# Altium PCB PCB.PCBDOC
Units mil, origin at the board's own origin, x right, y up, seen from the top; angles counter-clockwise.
Board outline 6000 x 4000 mil, 2 copper layers (Top Layer, Bottom Layer); 12 components, 5 nets, 24 pads, 0 vias.
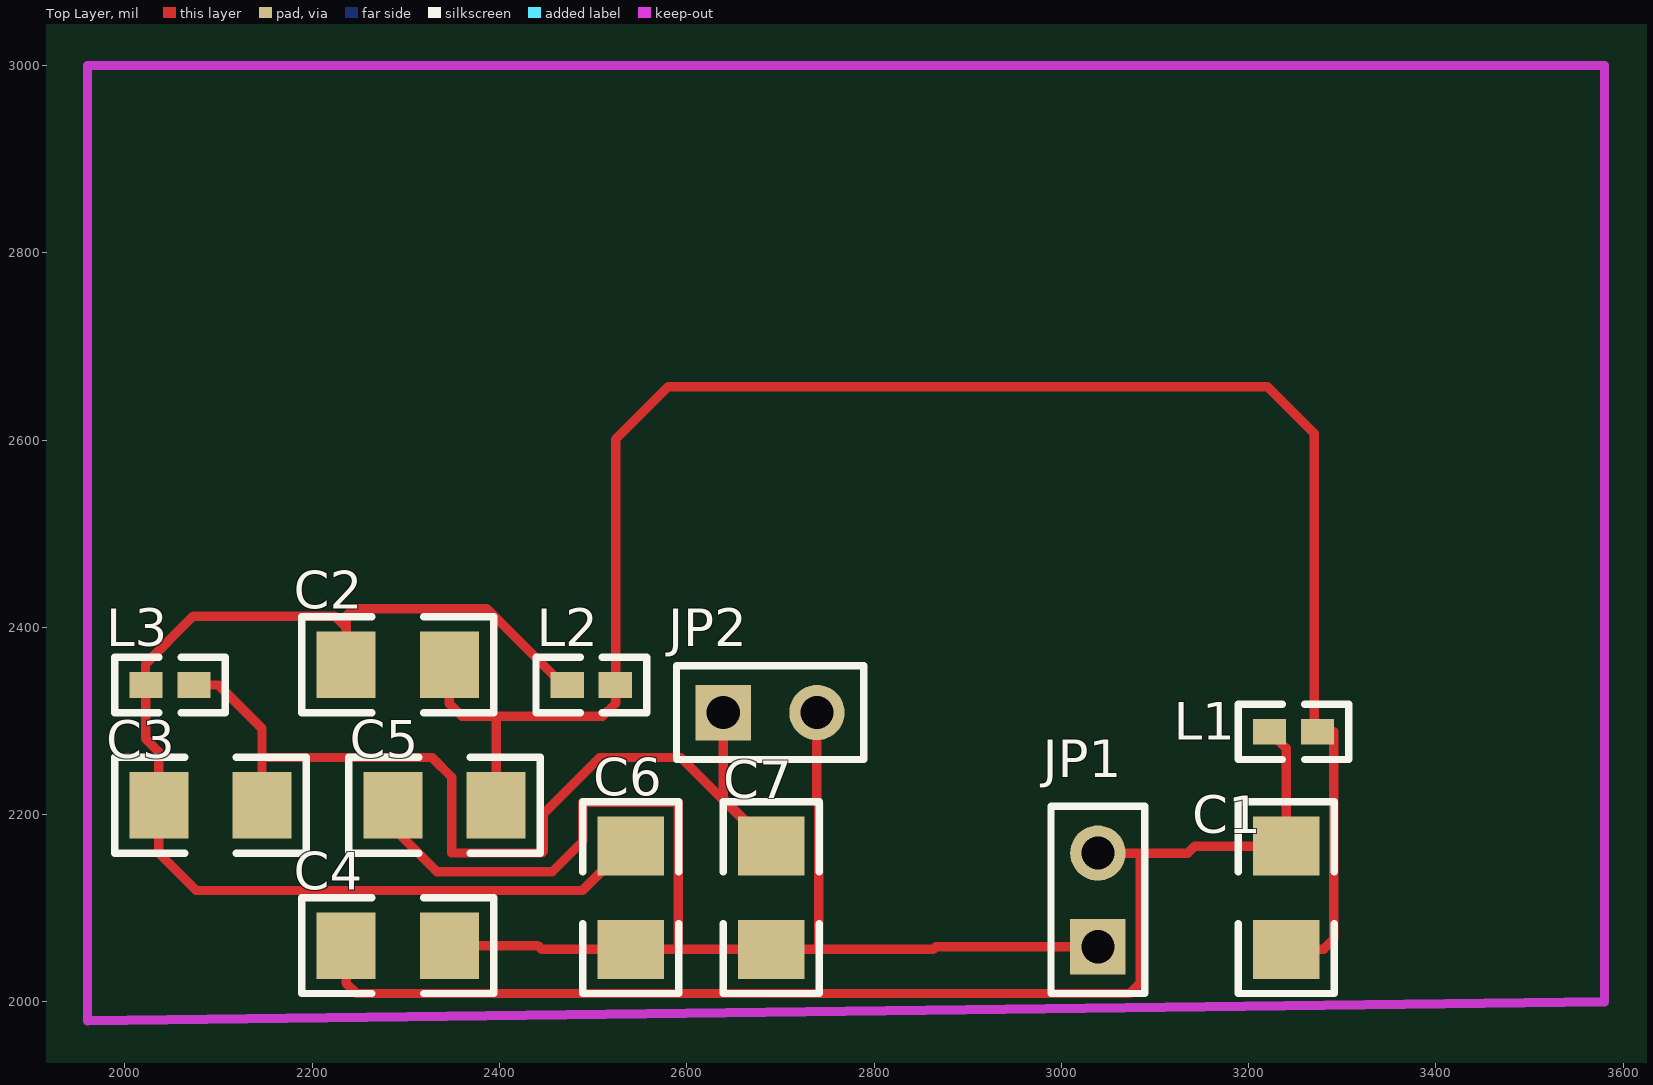
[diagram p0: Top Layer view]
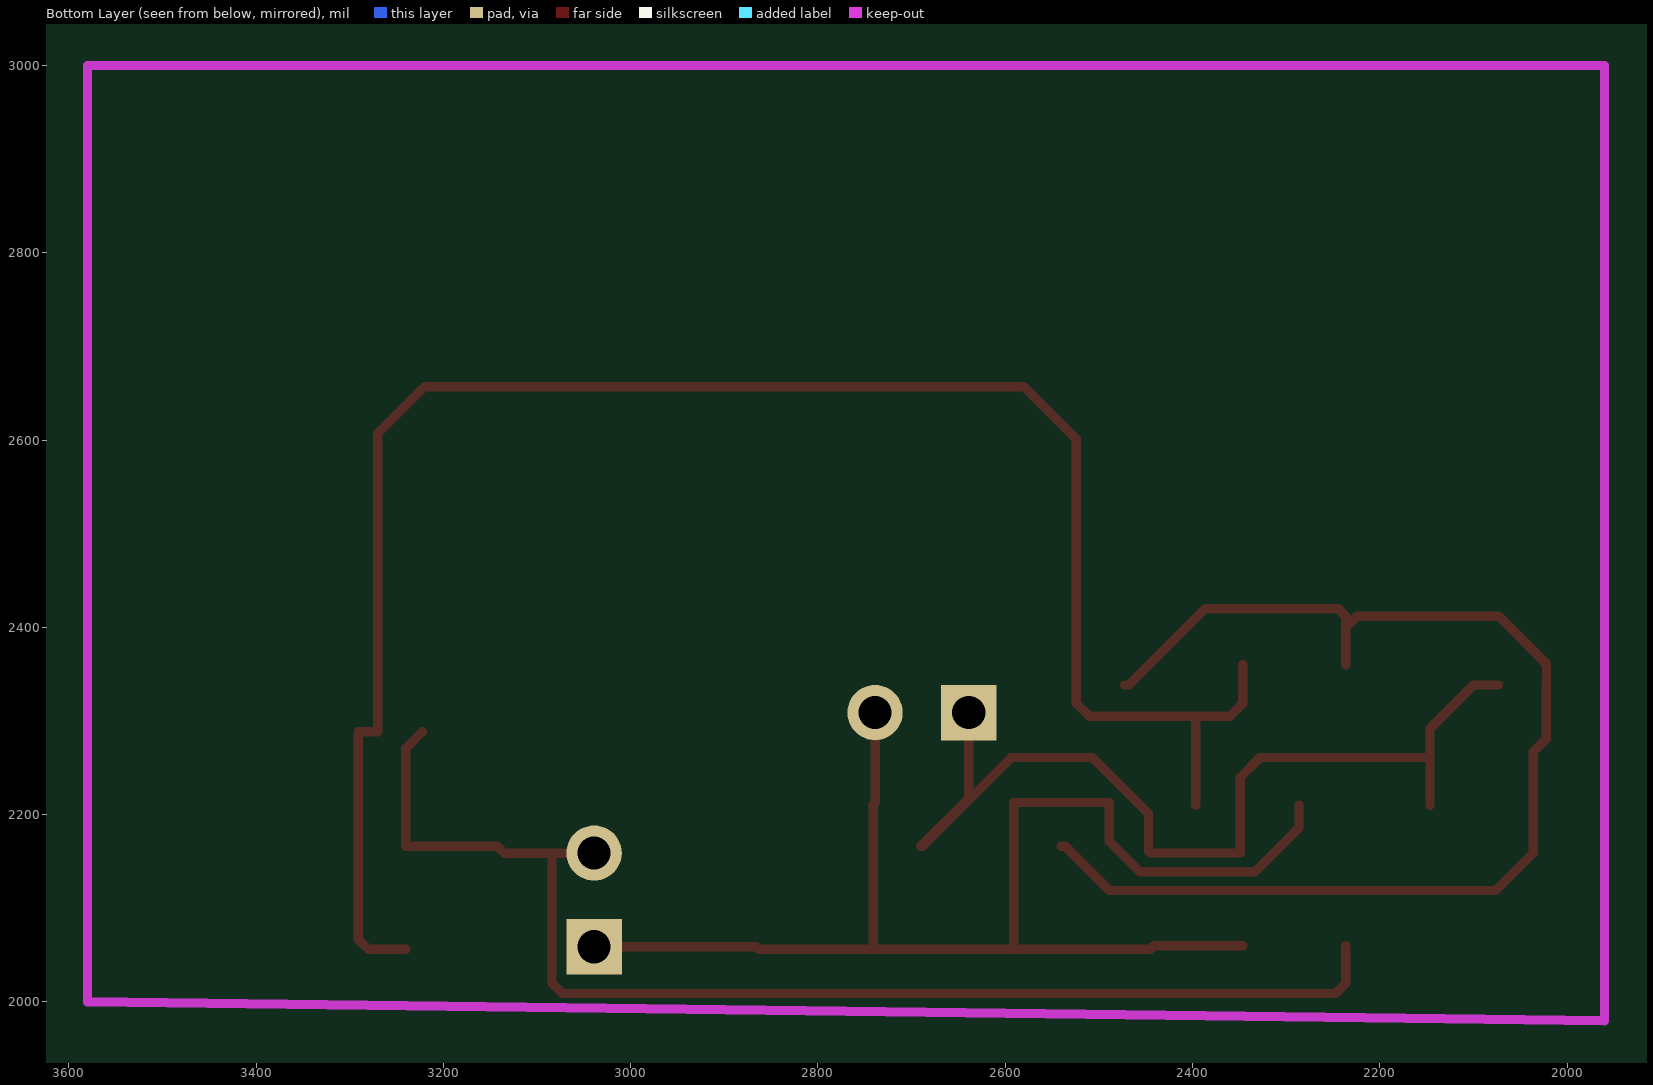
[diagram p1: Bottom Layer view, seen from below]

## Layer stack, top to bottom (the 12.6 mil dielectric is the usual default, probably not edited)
Top Layer: signal copper 1.4
Dielectric: dielectric 12.6, FR-4, Dk 4.8
Bottom Layer: signal copper 1.4

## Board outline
1000,1000 7000,1000 7000,5000 1000,5000

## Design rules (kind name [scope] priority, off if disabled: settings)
Clearance [All] p1: gap=10
ComponentClearance [All] p1: gap=10 collisioncheckmode=0
PolygonConnect [All] p1: connectstyle=Relief reliefconductorwidth=10 reliefentries=4 polygonreliefangle="90 Angle"
RoomDefinition Sheet1 [InComponentClass('Sheet1')] p1: confinementstyle=ConfineIn formatcopy=TRUE outline 1960,1980 3540,1980 3540,2960 1960,2960
RoutingLayers [All] p1: top layer=Horizontal bottom layer=Vertical
RoutingVias [All] p1: holewidth=28 width=50 viastyle="Through Hole" minholewidth=28 minwidth=50 maxholewidth=28 maxwidth=50
SolderMaskExpansion [All] p1: expansion=4
TestPointUsage [All] p1: valid=0 allowmultiple=FALSE
Testpoint [All] p1: side=15 testpointundercomponent=TRUE minsize=40 maxsize=100 preferedsize=60 minholesize=0 maxholesize=40 preferedholesize=32 testpointgrid=1 style=1023 order=1234567890
Width [All] p1: maxlimit=10 minlimit=10 preferedwidth=10
16 further rules are at their usual default settings.

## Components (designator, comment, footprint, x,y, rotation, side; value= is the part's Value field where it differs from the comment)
C1 "Cap Semi" C3216-1206 3240.12,2111.3 r270 top
C2 "Cap Semi" C3216-1206 2291.3,2360.12 r180 top
C3 "Cap Semi" C3216-1206 2091.3,2210.12 r0 top
C4 "Cap Semi" C3216-1206 2291.3,2060.12 r0 top
C5 "Cap Semi" C3216-1206 2341.3,2210.12 r180 top
C6 "Cap Semi" C3216-1206 2540.12,2111.3 r270 top
C7 "Cap Semi" C3216-1206 2690.12,2111.3 r270 top
JP1 "Header 2" HDR1X2 3038.94,2058.94 r90 top
JP2 "Header 2" HDR1X2 2638.94,2308.94 r0 top
L1 "Inductor" C1005-0402 3247.99,2288.46 r180 top
L2 "Inductor" C1005-0402 2497.99,2338.46 r0 top
L3 "Inductor" C1005-0402 2047.99,2338.46 r180 top

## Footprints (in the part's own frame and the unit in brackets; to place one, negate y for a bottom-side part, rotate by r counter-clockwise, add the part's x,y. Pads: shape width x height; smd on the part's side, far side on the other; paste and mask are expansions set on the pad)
C1005-0402 [mm]
  rect 0.9x0.7 smd: 1(-0.65,0) 2(0.65,0)
  silkscreen extent -1.5,-0.75 1.5,0.75
C3216-1206 [mm]
  rect 1.6x1.8 smd: 1(-1.4,0) 2(1.4,0)
  silkscreen extent -2.6,-1.3 2.6,1.3
HDR1X2 [mm]
  rect 1.5x1.5 hole 0.9: 1(0,0)
  round 1.5 hole 0.9: 2(2.54,0)
  silkscreen extent -1.27,-1.27 3.81,1.27

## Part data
C1 C2 C3 C4 C5 C6 C7: "Capacitor (Semiconductor SIM Model)"
JP1 JP2: "Header, 2-Pin"

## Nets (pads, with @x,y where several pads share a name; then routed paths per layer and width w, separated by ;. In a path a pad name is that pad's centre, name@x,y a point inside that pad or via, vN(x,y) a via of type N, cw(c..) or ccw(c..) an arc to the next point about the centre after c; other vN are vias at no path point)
GND: C4.2 C5.2 C6.2 C7.2 JP1.1 JP2.2 | length 1509
  Top Layer w10: C5.2 2286.18,2186 2333.18,2139 2456.42,2139 2489,2171.58 2489,2213 2591,2213 2591,2056.18 ; C4.2 2441,2060.12 2444.94,2056.18 C6.2 2591,2056.18 ; JP2.2 2738.94,2213 2741,2210.94 2741,2056.18 ; JP1.1 2865.76,2058.94 2863,2056.18 2741,2056.18 ; 2591,2056.18 C7.2 2741,2056.18
NetC1_1: C1.1 C4.1 JP1.2 L1.2 | length 1369.6
  Top Layer w10: C4.1 2236.18,2020 2247.18,2009 3073,2009 3084,2020 3084,2158.94 ; JP1.2 3084,2158.94 ; L1.2 3240.12,2270.75 C1.1 3142.48,2166.42 3135,2158.94 3084,2158.94
NetC1_2: C1.2 C2.1 C5.1 L1.1 L2.2 | length 2014
  Top Layer w10: C2.1 2346.42,2318.58 2360,2305 2396.42,2305 ; C5.1 2396.42,2305 ; L2.2 L2.2@2524,2338.46 ; C1.2 3280,2056.18 3291,2067.18 3291,2288.46 L1.1 3270,2288.46 3270,2607 3220,2657 2580,2657 2524,2601 L2.2@2524,2338.46 ; 2396.42,2305 2510,2305 2524,2319 L2.2@2524,2338.46
NetC2_2: C2.2 C3.1 C6.1 L2.1 L3.2 | length 1313.3
  Top Layer w10: C2.2 2236.18,2400 ; L2.1 2468,2338.46 2386.46,2420 2244.46,2420 2236.18,2411.72 2236.18,2400 ; C6.1 2536,2166.42 2488.58,2119 2076.18,2119 2036.18,2159 C3.1 2036.18,2267 2022.4,2280.78 L3.2 2022,2338.87 2022,2361 2073,2412 2224.18,2412 2236.18,2400
NetC3_2: C3.2 C7.1 JP2.1 L3.1 | length 1076
  Top Layer w10: L3.1 2100,2338.46 2146.42,2292.05 2146.42,2261 ; C3.2 2146.42,2261 ; JP2.1 2638.94,2217.6 C7.1 2688,2166.42 2593.42,2261 2507,2261 2447,2201 2447,2161 2445,2159 2349,2159 2349,2240 2328,2261 2146.42,2261

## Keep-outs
Keep-Out Layer:
  lines w10: 1960,1980 1960,3000 3580,3000 3580,2000 1960,1980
